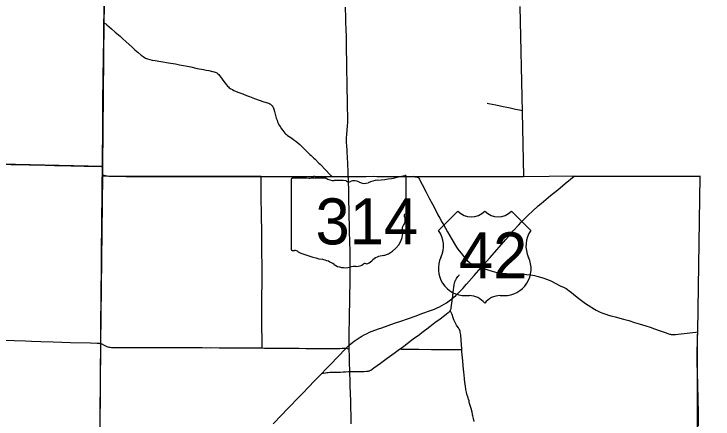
# Model space of a CAD drawing. Extents: x 1815539 to 1947826, y 273303 to 993194.
# Drawn here: x 1913070 to 1934195, y 953318 to 965571 of the extents above; entities that cross this region are included whole.
import ezdxf

# ---------------------------------------------------------------- set-up
doc = ezdxf.new("R2010")
doc.units = 0
for name, color, linetype in [('GM_X_County', 7, 'Continuous'), ('GM_X_County_Road', 7, 'Continuous'), ('GM_X_State_Route', 7, 'Continuous'), ('GM_X_Township', 7, 'Continuous'), ('GM_X_Township_Road', 7, 'Continuous'), ('GM_X_US_Route', 7, 'Continuous'), ('PV_X_Shoulder', 7, 'Continuous'), ('SC_Shading3', 7, 'Continuous')]:
    doc.layers.add(name, color=color, linetype=linetype)

msp = doc.modelspace()

# ---------------------------------------------------------------- linework, layer by layer
at = {"layer": 'GM_X_County'}
msp.add_lwpolyline([(1928357, 965797), (1928425, 962614), (1928467, 960653), (1930020, 960674), (1933801, 960656), (1933723, 955963), (1933713, 955812), (1933717, 954747), (1933720, 953054), (1933836, 950026), (1933939, 947488), (1934048, 942901), (1934067, 942157), (1934195, 936859)], dxfattribs=at)
at = {"layer": 'GM_X_County_Road'}
for points in [[(1926905, 958007), (1926971, 957977), (1927027, 957956), (1927097, 957932), (1927163, 957909), (1927188, 957902)], [(1927188, 957902), (1927222, 957892), (1927268, 957876), (1927423, 957823), (1927517, 957792), (1927595, 957768), (1927660, 957752), (1927708, 957742), (1927773, 957732), (1927838, 957725), (1927953, 957716), (1928221, 957701), (1928560, 957686), (1928674, 957677), (1928755, 957665), (1928803, 957656), (1928867, 957641), (1928977, 957610), (1929086, 957576), (1929164, 957548), (1929240, 957518), (1929314, 957485), (1929447, 957419), (1929579, 957351), (1929695, 957293), (1929753, 957262), (1929794, 957236), (1929848, 957199), (1929914, 957150), (1929977, 957099), (1930091, 957004), (1930180, 956934), (1930258, 956875), (1930338, 956817), (1930422, 956763), (1930616, 956641), (1930669, 956609), (1930726, 956580), (1930786, 956551), (1930831, 956531), (1930892, 956508), (1930957, 956487), (1931039, 956462), (1931147, 956434), (1931241, 956406), (1931490, 956337), (1931648, 956294), (1931820, 956242), (1931960, 956201), (1932164, 956137), (1932297, 956094), (1932431, 956048), (1932569, 955999), (1932753, 955931), (1932826, 955906), (1932879, 955890), (1932906, 955883), (1932929, 955879), (1932963, 955875), (1933010, 955872), (1933061, 955874), (1933143, 955882), (1933320, 955904), (1933583, 955936), (1933676, 955947), (1933733, 955951)], [(1926324, 956971), (1926326, 956995), (1926329, 957027), (1926343, 957156), (1926376, 957379), (1926387, 957442), (1926391, 957458), (1926395, 957473), (1926400, 957488), (1926414, 957518), (1926421, 957532), (1926446, 957574), (1926464, 957601), (1926483, 957626), (1926515, 957662), (1926526, 957674), (1926536, 957687)], [(1926256, 956606), (1926259, 956610), (1926266, 956624), (1926273, 956638), (1926278, 956653), (1926286, 956684), (1926296, 956749), (1926313, 956895), (1926324, 956971)], [(1924739, 955445), (1924848, 955527), (1925137, 955743), (1925321, 955880), (1925399, 955940), (1925476, 956000), (1925542, 956049), (1925635, 956116), (1925791, 956234), (1925949, 956350), (1926080, 956448), (1926145, 956498), (1926195, 956539), (1926219, 956561), (1926231, 956572), (1926241, 956584), (1926250, 956597), (1926256, 956606)], [(1910463, 955791), (1910484, 955790), (1910927, 955773), (1912123, 955726), (1912336, 955718), (1913073, 955691), (1913418, 955680), (1913598, 955675), (1913877, 955666), (1914254, 955655), (1914778, 955638), (1915384, 955619), (1915581, 955611), (1915640, 955608), (1915667, 955604), (1915693, 955599)], [(1915670, 952967), (1915670, 952983), (1915670, 953098), (1915673, 953312), (1915675, 953525), (1915676, 953755), (1915681, 954215), (1915682, 954412), (1915683, 954576), (1915683, 954707), (1915686, 955036), (1915690, 955266), (1915691, 955430), (1915693, 955551), (1915693, 955599)], [(1915693, 955599), (1915712, 955594), (1915725, 955590), (1915743, 955582), (1915759, 955574), (1915820, 955544), (1915879, 955516), (1915910, 955504), (1915941, 955495), (1915973, 955489), (1916022, 955483), (1916071, 955481), (1916252, 955480), (1916465, 955480), (1917399, 955481), (1918202, 955479), (1918350, 955479), (1918513, 955478), (1918661, 955477), (1918759, 955477), (1918874, 955476), (1919005, 955477), (1919267, 955476), (1919431, 955473), (1919595, 955472), (1919710, 955472), (1919792, 955472), (1919955, 955472), (1920086, 955471), (1920299, 955469), (1920398, 955469), (1920545, 955467), (1920567, 955467)], [(1920567, 955467), (1920643, 955465), (1920807, 955464), (1921069, 955463), (1921233, 955462), (1921405, 955460)], [(1921405, 955460), (1921413, 955460), (1921544, 955459), (1921692, 955458), (1921889, 955456), (1922003, 955453), (1922118, 955454), (1922281, 955455), (1922380, 955454), (1922560, 955453), (1922675, 955452), (1922773, 955452), (1922921, 955455), (1922993, 955457), (1923107, 955459)], [(1923107, 955459), (1923142, 955453), (1923178, 955443), (1923201, 955436)], [(1923217, 954757), (1923377, 954755), (1923475, 954757), (1923557, 954759), (1923655, 954760), (1923720, 954762), (1923752, 954765), (1923768, 954767), (1923784, 954770), (1923799, 954774), (1923815, 954780), (1923829, 954786), (1923857, 954801), (1923898, 954829), (1923950, 954869), (1924043, 954935), (1924150, 955011), (1924230, 955068), (1924348, 955156), (1924559, 955312), (1924717, 955429), (1924739, 955445)], [(1922380, 954706), (1922426, 954705), (1922480, 954711), (1922528, 954721), (1922564, 954728), (1922612, 954731), (1922677, 954734), (1922855, 954739), (1922936, 954740), (1923020, 954745), (1923085, 954750), (1923178, 954756), (1923217, 954757)]]:
    msp.add_lwpolyline(points, dxfattribs=at)
at = {"layer": 'GM_X_State_Route'}
for points in [[(1923199, 955548), (1923199, 955574), (1923198, 955607), (1923198, 955706), (1923200, 955820), (1923201, 955918), (1923202, 956000), (1923207, 956279), (1923210, 956427), (1923213, 956558), (1923217, 956788), (1923218, 956919), (1923222, 957083), (1923227, 957395), (1923228, 957576), (1923229, 957904), (1923230, 958134), (1923229, 958265), (1923226, 958429), (1923219, 958643), (1923217, 958790), (1923214, 958889), (1923210, 959102), (1923201, 959513), (1923196, 959710), (1923192, 959857), (1923191, 959939), (1923185, 960284), (1923181, 960448), (1923179, 960581), (1923174, 960652), (1923172, 960696), (1923169, 960827), (1923162, 961008), (1923157, 961106), (1923153, 961172), (1923147, 961270), (1923142, 961352), (1923135, 961450), (1923126, 961581), (1923121, 961679), (1923120, 961744), (1923122, 961826), (1923128, 961924), (1923152, 962185), (1923158, 962283), (1923160, 962382), (1923159, 962513), (1923154, 962710), (1923152, 962808), (1923148, 963022), (1923142, 963251), (1923140, 963399), (1923140, 963547), (1923134, 963826), (1923130, 964055), (1923130, 964154), (1923122, 964465), (1923120, 964563), (1923117, 964744), (1923114, 964892), (1923106, 965105), (1923102, 965318), (1923098, 965449), (1923091, 965777)], [(1923255, 953496), (1923252, 953597), (1923246, 953843), (1923239, 954106), (1923232, 954302), (1923228, 954433), (1923226, 954515), (1923222, 954679), (1923219, 954744), (1923217, 954757), (1923217, 954825), (1923212, 954972), (1923208, 955102), (1923207, 955195), (1923207, 955247), (1923206, 955282), (1923204, 955361), (1923201, 955436), (1923201, 955460), (1923199, 955525), (1923199, 955548)], [(1923263, 953171), (1923256, 953433), (1923255, 953496)]]:
    msp.add_lwpolyline(points, dxfattribs=at)
at = {"layer": 'GM_X_Township'}
for points in [[(1916031, 987559), (1916031, 987390), (1916016, 983574), (1916012, 983206), (1915968, 979502), (1915954, 977797), (1915930, 976934), (1915938, 976821), (1915894, 974189), (1915874, 972112), (1915857, 970374), (1915816, 966860), (1915806, 966233), (1915788, 965343), (1915744, 960965)], [(1889423, 961536), (1894728, 961453), (1894730, 961440), (1894815, 961451), (1899962, 961375), (1907847, 961159), (1910485, 961083), (1915744, 960965), (1915744, 960672), (1915689, 955598), (1915669, 952972), (1915640, 948490), (1915630, 947868), (1915624, 947610), (1915561, 944982), (1915495, 939674)], [(1915744, 960672), (1915744, 960965)], [(1915744, 960672), (1920541, 960662), (1921738, 960652), (1922124, 960663), (1922164, 960668), (1922719, 960651), (1923180, 960652), (1925154, 960663), (1925224, 960656), (1928467, 960653), (1930020, 960674), (1933801, 960656)]]:
    msp.add_lwpolyline(points, dxfattribs=at)
at = {"layer": 'GM_X_Township_Road'}
for points in [[(1915790, 965307), (1915790, 965312), (1915794, 965542), (1915796, 965607), (1915797, 965673), (1915798, 965754), (1915803, 965968), (1915807, 966132), (1915807, 966222)], [(1915744, 960960), (1915744, 960987), (1915745, 961085), (1915745, 961151), (1915746, 961298), (1915748, 961380), (1915750, 961528), (1915752, 961708), (1915754, 961937), (1915755, 962036), (1915755, 962134), (1915755, 962249), (1915757, 962478), (1915757, 962592), (1915758, 962789), (1915759, 962969), (1915760, 963248), (1915761, 963314), (1915763, 963428), (1915764, 963477), (1915765, 963559), (1915770, 963903), (1915773, 964001), (1915779, 964329), (1915780, 964443), (1915783, 964631), (1915785, 964804), (1915785, 964952), (1915786, 965116), (1915788, 965198), (1915790, 965307)], [(1915790, 965307), (1915828, 965279), (1915842, 965269), (1915880, 965238), (1916017, 965121), (1916129, 965025), (1916278, 964896), (1916351, 964830), (1916459, 964729), (1916628, 964574), (1916724, 964485), (1916774, 964442), (1916824, 964400), (1916913, 964328), (1916979, 964279), (1917019, 964251), (1917048, 964235), (1917078, 964222), (1917109, 964211), (1917172, 964194), (1917251, 964175), (1917332, 964159), (1917510, 964129), (1917737, 964094), (1917947, 964059), (1918076, 964035), (1918253, 964000), (1918414, 963967), (1918606, 963926), (1918798, 963886), (1918879, 963870), (1918959, 963856), (1919072, 963834), (1919120, 963823), (1919151, 963813), (1919181, 963800), (1919196, 963792), (1919210, 963783), (1919223, 963773), (1919235, 963763), (1919258, 963739), (1919279, 963714), (1919308, 963674), (1919414, 963528), (1919494, 963424), (1919525, 963386), (1919548, 963362), (1919572, 963341), (1919599, 963321), (1919626, 963304), (1919670, 963281), (1919714, 963260), (1919760, 963240), (1919835, 963209), (1919926, 963172), (1919987, 963150), (1920094, 963108), (1920185, 963071), (1920339, 963013), (1920478, 962963), (1920618, 962917), (1920728, 962884), (1920775, 962868), (1920804, 962855), (1920818, 962846), (1920832, 962837), (1920844, 962826), (1920856, 962815), (1920867, 962803), (1920878, 962790), (1920887, 962777), (1920896, 962763), (1920903, 962748), (1920916, 962718), (1920926, 962687), (1920942, 962623), (1920974, 962496), (1920998, 962417), (1921019, 962355), (1921036, 962310), (1921057, 962265), (1921079, 962222), (1921112, 962165), (1921155, 962095), (1921192, 962041), (1921222, 962002), (1921254, 961965), (1921277, 961942), (1921302, 961920), (1921341, 961891), (1921382, 961863), (1921465, 961810), (1921532, 961764), (1921585, 961725), (1921648, 961672), (1921709, 961618), (1921780, 961550), (1921863, 961470), (1921933, 961402), (1922015, 961322), (1922051, 961288), (1922134, 961209), (1922169, 961175), (1922285, 961059), (1922319, 961024), (1922491, 960848), (1922617, 960719), (1922648, 960689), (1922662, 960677), (1922674, 960668), (1922689, 960659), (1922702, 960652)], [(1927375, 962872), (1927407, 962866), (1927632, 962822), (1927856, 962776), (1927968, 962752), (1928063, 962731), (1928223, 962696), (1928287, 962683), (1928351, 962670), (1928428, 962652)], [(1910489, 961081), (1910686, 961075), (1911095, 961063), (1911390, 961055), (1911522, 961051), (1911620, 961050), (1911751, 961048), (1911833, 961046), (1912178, 961037), (1912604, 961030), (1912982, 961019), (1913140, 961016)], [(1913140, 961016), (1913324, 961014), (1913543, 961010), (1914015, 960998), (1914113, 960995), (1914293, 960991), (1914557, 960986), (1914801, 960980), (1915015, 960975), (1915196, 960971), (1915409, 960968), (1915541, 960965), (1915714, 960961), (1915744, 960960)], [(1915744, 960960), (1915743, 960855), (1915741, 960757), (1915741, 960707)], [(1915717, 958184), (1915719, 958332), (1915719, 958480), (1915719, 958611), (1915720, 958725), (1915723, 958873), (1915725, 959004), (1915726, 959152), (1915728, 959348), (1915729, 959430), (1915730, 959561), (1915734, 959872), (1915736, 960003), (1915737, 960184), (1915738, 960364), (1915739, 960479), (1915740, 960577), (1915741, 960707)], [(1915741, 960707), (1915757, 960702), (1915824, 960681), (1915856, 960675), (1915889, 960671), (1915938, 960667), (1916036, 960664), (1916266, 960660), (1916464, 960657), (1916806, 960657), (1916939, 960657), (1917053, 960658), (1917300, 960656), (1917512, 960656), (1917759, 960653), (1918054, 960651), (1918217, 960653), (1918349, 960653), (1918481, 960653), (1918659, 960653), (1918804, 960652), (1918924, 960653), (1919056, 960652), (1919185, 960653), (1919364, 960657), (1919579, 960658), (1919745, 960656), (1919908, 960655), (1920085, 960658), (1920318, 960657), (1920515, 960658), (1920539, 960658)], [(1920539, 960658), (1920597, 960657), (1920743, 960657), (1920890, 960655), (1921165, 960652), (1921348, 960651), (1921459, 960651), (1921642, 960649), (1921760, 960646), (1921810, 960644), (1921825, 960642)], [(1920558, 959102), (1920556, 959163), (1920554, 959294), (1920552, 959474), (1920549, 959638), (1920545, 959900), (1920543, 960080), (1920541, 960358), (1920540, 960506), (1920539, 960604), (1920539, 960639), (1920539, 960658)], [(1921825, 960642), (1921842, 960640), (1921874, 960634), (1921937, 960617), (1921970, 960609), (1921986, 960607), (1922002, 960606), (1922018, 960607), (1922034, 960611), (1922049, 960618), (1922076, 960634), (1922091, 960643)], [(1922091, 960643), (1922103, 960650), (1922117, 960656), (1922131, 960659), (1922152, 960660), (1922176, 960659), (1922221, 960659), (1922352, 960656), (1922549, 960654), (1922702, 960652)], [(1922702, 960652), (1922779, 960651), (1923006, 960652), (1923154, 960652), (1923174, 960652)], [(1923174, 960652), (1923303, 960654), (1923510, 960654), (1923711, 960657), (1923925, 960661), (1924034, 960658), (1924197, 960656), (1924286, 960656), (1924465, 960653), (1924597, 960651), (1924779, 960652), (1924927, 960654), (1925058, 960653), (1925173, 960651), (1925194, 960649)], [(1925194, 960649), (1925205, 960648), (1925238, 960643), (1925254, 960638), (1925269, 960633), (1925284, 960625), (1925296, 960615), (1925306, 960602), (1925323, 960574), (1925360, 960501), (1925405, 960413), (1925524, 960179), (1925629, 959975), (1925715, 959822), (1925776, 959707), (1925882, 959498), (1925935, 959394), (1926008, 959265), (1926059, 959181), (1926112, 959092), (1926174, 958985), (1926246, 958856), (1926311, 958739), (1926408, 958571), (1926442, 958515), (1926480, 958461), (1926520, 958408), (1926582, 958332), (1926614, 958295), (1926646, 958258), (1926709, 958182), (1926776, 958108), (1926812, 958074), (1926835, 958054), (1926859, 958034), (1926905, 958007)], [(1930001, 960669), (1930091, 960667), (1930156, 960663), (1930205, 960663), (1930271, 960663), (1930369, 960664), (1930419, 960665), (1930500, 960666), (1930550, 960666), (1930664, 960665), (1930713, 960665), (1930795, 960664), (1930910, 960664), (1931025, 960663), (1931123, 960662), (1931238, 960662), (1931369, 960663), (1931550, 960663), (1931648, 960664), (1931829, 960665), (1931927, 960666), (1932058, 960666), (1932124, 960665), (1932206, 960664), (1932272, 960664), (1932337, 960665), (1932452, 960665), (1932550, 960664), (1932682, 960663), (1932813, 960663), (1933059, 960665), (1933240, 960666), (1933338, 960667), (1933519, 960668), (1933683, 960667), (1933822, 960668)], [(1920566, 957271), (1920567, 957313), (1920567, 957411), (1920569, 957640), (1920569, 957722), (1920568, 957837), (1920566, 958082), (1920565, 958246), (1920564, 958443), (1920562, 958574), (1920560, 958688), (1920560, 958803), (1920560, 958934), (1920559, 959065), (1920558, 959102)], [(1915693, 955599), (1915692, 955652), (1915694, 955741), (1915694, 955856), (1915695, 956069), (1915697, 956200), (1915699, 956463), (1915702, 956725), (1915704, 957004), (1915705, 957168), (1915709, 957413), (1915710, 957593), (1915712, 957791), (1915716, 957938), (1915716, 958070), (1915717, 958184)], [(1920565, 955995), (1920565, 956086), (1920563, 956299), (1920561, 956397), (1920560, 956512), (1920559, 956659), (1920561, 956806), (1920563, 956921), (1920564, 957117), (1920565, 957199), (1920566, 957271)], [(1926600, 955426), (1926600, 955436), (1926591, 955584), (1926583, 955698), (1926570, 955862), (1926564, 955910), (1926558, 955942), (1926550, 955973), (1926539, 956004), (1926526, 956033), (1926501, 956075), (1926465, 956130), (1926448, 956157), (1926424, 956201), (1926394, 956259), (1926367, 956319), (1926345, 956381), (1926312, 956476), (1926276, 956565), (1926256, 956606)], [(1920567, 955467), (1920567, 955497), (1920567, 955710), (1920566, 955824), (1920565, 955995)], [(1933730, 955808), (1933732, 955882), (1933733, 955951)], [(1933760, 953098), (1933758, 953287), (1933757, 953402), (1933754, 953582), (1933754, 953664), (1933751, 953762), (1933744, 954041), (1933740, 954221), (1933734, 954451), (1933730, 954615), (1933723, 954828), (1933719, 954910), (1933717, 954972), (1933716, 955106), (1933717, 955171), (1933717, 955237), (1933721, 955434), (1933723, 955581), (1933729, 955762), (1933730, 955808)], [(1924739, 955445), (1924767, 955437), (1924781, 955432), (1924787, 955431), (1924794, 955430), (1925041, 955433), (1925305, 955430), (1925689, 955426), (1925843, 955422), (1925986, 955423), (1926200, 955425), (1926368, 955426), (1926569, 955426), (1926600, 955426)], [(1926982, 953243), (1926959, 953338), (1926939, 953416), (1926931, 953447), (1926928, 953462), (1926912, 953525), (1926884, 953634), (1926875, 953665), (1926864, 953695), (1926849, 953758), (1926840, 953789), (1926828, 953836), (1926821, 953868), (1926812, 953899), (1926806, 953914), (1926793, 953961), (1926788, 953976), (1926782, 953991), (1926759, 954070), (1926743, 954134), (1926727, 954214), (1926711, 954311), (1926698, 954425), (1926685, 954539), (1926673, 954653), (1926664, 954734), (1926645, 954930), (1926634, 955077), (1926607, 955355), (1926600, 955426)]]:
    msp.add_lwpolyline(points, dxfattribs=at)
at = {"layer": 'GM_X_US_Route'}
for points in [[(1924091, 956045), (1924186, 956079), (1924573, 956215), (1924790, 956292), (1924959, 956353), (1925223, 956444), (1925393, 956506), (1925686, 956611), (1925778, 956646), (1925854, 956679), (1925928, 956714), (1926000, 956752), (1926072, 956794), (1926141, 956838), (1926222, 956894), (1926301, 956953), (1926324, 956971), (1926365, 957005), (1926426, 957059), (1926498, 957127), (1926567, 957198), (1926634, 957270), (1926743, 957393), (1926981, 957664), (1927188, 957902), (1927228, 957949), (1927457, 958207), (1927932, 958750), (1928082, 958924), (1928159, 959010), (1928323, 959193), (1928401, 959277), (1928538, 959418), (1928620, 959498), (1928728, 959598), (1928911, 959763), (1928998, 959837), (1929288, 960078), (1929504, 960254), (1929732, 960443), (1930001, 960669)], [(1921433, 953726), (1921463, 953758), (1921577, 953876), (1921692, 953993), (1921829, 954134), (1921955, 954263), (1922170, 954489), (1922380, 954706), (1922478, 954807), (1922638, 954972), (1923093, 955445), (1923107, 955459), (1923163, 955515), (1923199, 955548), (1923211, 955559), (1923299, 955632), (1923351, 955672), (1923445, 955738), (1923527, 955792), (1923583, 955825), (1923655, 955864), (1923743, 955908), (1923818, 955942), (1923893, 955972), (1924091, 956045)], [(1920905, 953178), (1921156, 953438), (1921338, 953628), (1921433, 953726)]]:
    msp.add_lwpolyline(points, dxfattribs=at)
at = {"layer": 'PV_X_Shoulder'}
for p, q in [((1926484, 959603), (1925904, 959023)), ((1928689, 959023), (1928109, 959603)), ((1926716, 957051), (1926832, 957051)), ((1927761, 957051), (1927877, 957051))]:
    msp.add_line(p, q, dxfattribs=at)
for centre, radius, start, end in [((1926890, 960017), 580, 225.573, 314.427), ((1927703, 960017), 580, 225.573, 314.427), ((1925239, 958557), 812, 334.5471, 35.0009), ((1929354, 958557), 812, 144.9991, 205.4529), ((1926707, 957863), 812, 154.8319, 270.6383), ((1927886, 957863), 812, 269.3617, 25.1681), ((1926832, 956471), 580, 36.8699, 90), ((1927761, 956471), 580, 90, 143.1301)]:
    msp.add_arc(centre, radius, start, end, dxfattribs=at)
at = {"layer": 'SC_Shading3'}
for p, q in [((1921447, 960565), (1921447, 958452)), ((1922500, 960601), (1921481, 960601)), ((1924927, 959548), (1924927, 960654)), ((1924927, 959549), (1924927, 959548))]:
    msp.add_line(p, q, dxfattribs=at)
for centre, major_axis, start_param, end_param in [((1921487, 960570), (40.3, 0), 1.712693, 3.28349), ((1922743, 960847), (391, 0), 4.042523, 4.731795), ((1923688, 963483), (3691, 0), 4.814394, 5.042369), ((1924889, 960658), (38.7, 0), 6.141152, 7.989035), ((1922873, 959415), (1404, 0), 1.404758, 1.657858), ((1923192, 960581), (113, 0), 3.836095, 5.185415), ((1923357, 960336), (235, 0), 0.950623, 2.079405), ((1923660, 960671), (282, 0), 4.081561, 5.145723), ((1924158, 959956), (743, 0), 1.699011, 2.107814), ((1924918, 959467), (60, 0), 1.883978, 3.671073), ((1924886, 959544), (41.5, 0), 5.05454, 6.418171), ((1924537, 959327), (360, 0), 5.934695, 6.695948), ((1925066, 959086), (262, 0), 2.387724, 3.262537), ((1923894, 958945), (923, 0), 5.101752, 6.440018), ((1921487, 958447), (40.7, 0), 3.00124, 4.508301), ((1921493, 958663), (310, 0), 4.665946, 4.897461), ((1921557, 958330), (112, 0), 0.519207, 1.627899), ((1922970, 960229), (2665, 0), 4.195997, 4.488961), ((1924284, 957859), (506, 0), 1.647645, 2.488434), ((1922175, 957502), (834, 0), 0.823519, 1.323587), ((1923643, 958247), (298, 0), 4.937069, 5.64225), ((1923077, 958319), (529, 0), 4.026481, 4.996735), ((1923383, 957589), (435, 0), 1.495662, 1.94098), ((1923422, 958161), (282, 0), 4.691044, 5.507374), ((1923677, 957956), (79.4, 0), 1.147584, 2.315152)]:
    msp.add_ellipse(centre, major_axis=major_axis, ratio=0.8, start_param=start_param, end_param=end_param, dxfattribs=at)

# ---------------------------------------------------------------- texts
at = {"layer": 'PV_X_Shoulder'}
msp.add_text('42', height=1392.2, dxfattribs=at).set_placement((1926513, 957573))
at = {"layer": 'SC_Shading3'}
msp.add_text('314', height=1392.2, dxfattribs=at).set_placement((1922181, 958601))

doc.saveas('drawing.dxf')
